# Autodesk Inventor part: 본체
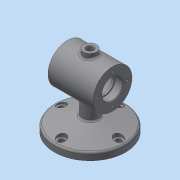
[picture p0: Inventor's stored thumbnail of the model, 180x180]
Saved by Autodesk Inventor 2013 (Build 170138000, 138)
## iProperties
Created: 2018-12
Part Number: 본체
Material: 일반
Document SubType Name: Modeling
Designer: dgall
Density: 1 g/cm^3
Author: dgall
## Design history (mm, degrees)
sketch "스케치1"
  geometry: C1 r 55 at (0, 0); 1 further point
  constraints: 1 centre point, 1 coincident
  dimensions: "d3" = 110 diameter of C1
extrude "돌출1" new body sketch "스케치1" distance "d0" = 11; taper "d1" = 0 deg
sketch "스케치3"
  geometry: C1 r 30 at (0, 75); 1 further point
  constraints: 1 centre point, 1 vertical alignment
  dimensions: "d6" = 75 distance of point (0, 0) C1.centre; "d7" = 60 diameter of C1
extrude "돌출2" join sketch "스케치3" stored distance "d8" = 70; taper "d9" = 0 deg
sketch "스케치4"
  geometry: C1 r 30 at (0, 0) reference; C2 r 14 at (0, 0); 1 further point
  constraints: 1 centre point, 1 coincident
  dimensions: "d10" = 28 diameter of C2
extrude "돌출3" cut sketch "스케치4" distance "d12" = 70; taper "d13" = 0 deg
node "작업 평면1"
sketch "스케치5"
  geometry: C1 r 14 at (0, 0) reference; C2 r 25 at (0, 0); 1 further point
  constraints: 1 centre point, 1 coincident
  dimensions: "d15" = 50 diameter of C2
extrude "돌출4" cut sketch "스케치5" stored distance "d17" = 40; taper "d18" = 0 deg
hole "구멍1" diameter "d21" = 32; stored, may be unused: countersink angle "d25" = 90 deg, drill point angle "d27" = 0 deg; dims "d19" = 10, "d20" = 10, "d22" = 6, "d23" = 4, "d24" = 2, "d26" = 12
hole "구멍2" diameter "d30" = 32; stored, may be unused: countersink angle "d34" = 90 deg, drill point angle "d36" = 0 deg; dims "d28" = 10, "d29" = 10, "d31" = 6, "d32" = 4, "d33" = 2, "d35" = 12
sketch "스케치6"
  geometry: C1 r 55 at (0, 0) reference; C2 r 12 at (0, 0)
  constraints: 1 centre point, 1 coincident
  dimensions: "d37" = 24 diameter of C2
extrude "돌출5" join sketch "스케치6" stored distance "d39" = 40; taper "d40" = 0 deg
sketch "스케치7"
  geometry: L1 (55, 11)-(-55, 11) reference; L2 (-55, 0)-(55, 0) reference; L3 (55, 0)-(55, 11) reference; L4 (12, 11)-(12, 45) reference; L5 (12, 11)-(12, 45) reference; L6 (55, 11)-(-55, 11) reference; L7 (55, 11)-(5, 24.397); L8 (0, 0)-(0, 105); L9 (35, 105)-(-35, 105) reference; L10 (5, 24.397)-(5, 11); L11 (55, 11)-(5, 11)
  constraints: 8 end point, 2 perpendicular, 1 midpoint, 1 point on line
  dimensions: "d42" = 75 deg angle of L7 L3; "d43" = 50 horizontal distance of L3.end L7.end
revolve "회전1" sketch "스케치7" stored, may be unused: angle "d44" = 90 deg
sketch "스케치8"
  geometry: C1 r 55 at (0, 0) reference; 4 further points
  constraints: 2 horizontal alignment, 2 vertical alignment
  dimensions: "d47" = 88 distance of point (44, 0) point (-44, 0); "d49" = 88 distance of point (0, 44) point (0, -44); "d50" = 44 distance of C1.centre point (-44, 0); "d51" = 44 distance of point (0, -44) C1.centre
hole "구멍3" sketch "스케치8" at (0, 44), (-44, 0), (0, -44), (44, 0) diameter "d52" = 9; stored, may be unused: countersink angle "d56" = 90 deg, drill point angle "d58" = 0 deg; dims "d53" = 6, "d54" = 4, "d55" = 2, "d57" = 30
node "작업 평면3"
sketch "스케치9"
  geometry: C1 r 4.5 at (0, 44) reference; C2 r 4.5 at (-44, 0) reference; C3 r 4.5 at (0, -44) reference; C4 r 4.5 at (44, 0) reference; C5 r 7 at (0, 44); C6 r 7 at (-44, 0); C7 r 7 at (44, 0); C8 r 7 at (0, -44); 1 further point
  constraints: 4 centre point, 4 coincident, 3 equal radius
  dimensions: "d61" = 14 diameter of C5
extrude "돌출6" cut sketch "스케치9" distance "d63" = 15; taper "d64" = 0 deg
sketch "스케치10"
  geometry: C1 r 16 at (0, 0) reference; 5 further points
  constraints: 2 horizontal alignment, 2 vertical alignment
  dimensions: "d65" = 46 distance of point (23, 0) point (-23, 0); "d67" = 46 distance of point (0, 23) point (0, -23); "d68" = 23 distance of C1.centre point (0, 23); "d69" = 23 distance of C1.centre point (-23, 0)
hole "구멍4" sketch "스케치10" at (0, 23), (-23, 0), (0, -23), (23, 0) diameter "d70" = 3.242; stored, may be unused: countersink angle "d74" = 90 deg, drill point angle "d76" = 118 deg; dims "d71" = 8, "d72" = 4, "d73" = 2, "d75" = 10
node "작업 평면4"
sketch "스케치11"
  geometry: C1 r 10 at (0, 0); C2 r 5 at (0, 0); 1 further point
  constraints: 2 centre point, 2 coincident
  dimensions: "d78" = 20 diameter of C1; "d79" = 10 diameter of C2
extrude "돌출7" join sketch "스케치11" stored distance "d80" = 15; taper "d81" = 0 deg
chamfer "모따기1" distance "d82" = 1; stored, may be unused: second distance "d83" = 2, angle "d84" = 45 deg
fillet "모깎기1" dims "d85" = 3
node "작업 평면6"
sketch "스케치13"
  geometry: L1 (-35, 105)-(-35, 45) reference; 2 further points
  constraints: 1 other
  dimensions: "d90" = 35 distance from line of L1 point (0, 75); "d92" = 30 vertical distance of L1.start point (0, 75)
feature "엠보싱1" sketch "스케치13" dims "d0" = 11, "d1" = 0, "d93" = 0.5, "d94" = 0
extrude "돌출8" cut sketch "스케치11" distance "d95" = 15; taper "d96" = 0 deg
fillet "모깎기2" dims "d99" = 0.3
fillet "모깎기3" dims "d100" = 3
node "솔리드1"
mirror "대칭1"
node "투영된 루프1"
other parameters: "d14" = -35, "d60" = -25, "d77" = -112
